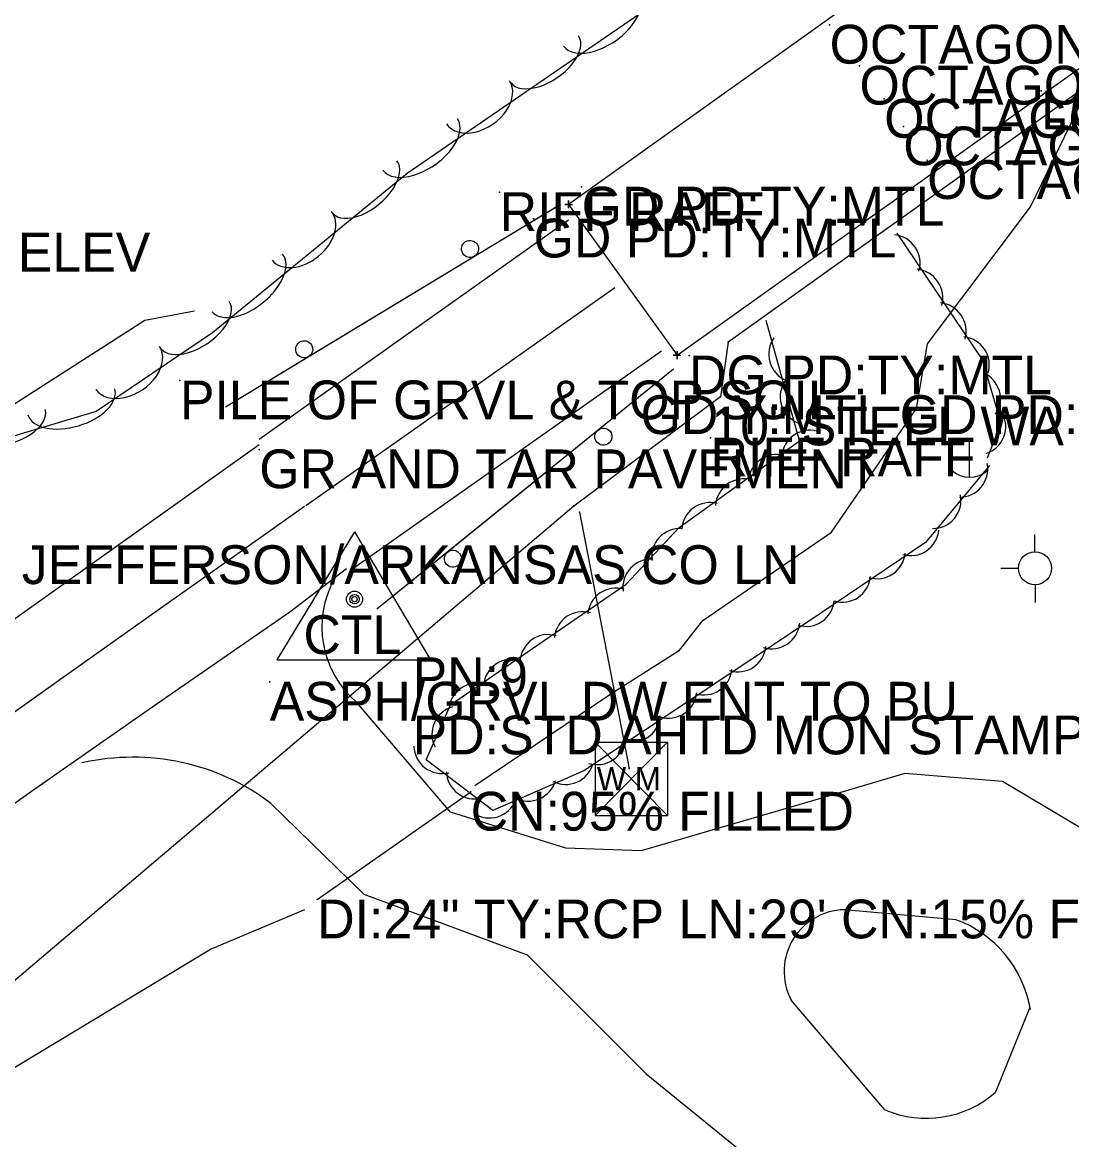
# Model space of a CAD drawing. Extents: x 1451369 to 1458940, y 1868647 to 1875095.
# Drawn here: x 1454143.2 to 1454278.5, y 1871314.6 to 1871458.6 of the extents above; entities that cross this region are included whole.
import ezdxf

# ---------------------------------------------------------------- set-up
doc = ezdxf.new("R2010")
doc.units = 0
for name, color, linetype in [('E_Const Align', 7, 'Continuous'), ('E_Existing_ROW', 7, 'Continuous'), ('E_No Plot', 7, 'Continuous'), ('E_PL and Hook', 7, 'Continuous'), ('E_Proposed ROW and Easements', 7, 'Continuous'), ('E_Quarter Section Line', 7, 'Continuous'), ('E_Row Point', 7, 'Continuous'), ('E_ROW Point Number', 7, 'Continuous'), ('E_Tract Number', 7, 'Continuous'), ('R_No Plot', 7, 'Continuous'), ('S_EDGE_PAVEMENT', 7, 'Continuous'), ('S_EXIST_ROW', 7, 'Continuous'), ('S_GUARDRAIL', 7, 'Continuous'), ('S_MISC_STRUCTURES_ANNOT', 7, 'Continuous'), ('S_PARKING', 7, 'Continuous'), ('S_PAVEMENT_CROWN', 7, 'Continuous'), ('S_PRIMARY_CTL_ANNOT', 7, 'Continuous'), ('S_SECONDARY_CTL_ANNOT', 7, 'Continuous'), ('S_SIDE_DRAIN_ANNOT', 7, 'Continuous'), ('S_SURVEY_TEXT_ANNOT', 7, 'Continuous')]:
    doc.layers.add(name, color=color, linetype=linetype)

msp = doc.modelspace()

# ---------------------------------------------------------------- linework, layer by layer
at = {"layer": 'E_Const Align'}
for p, q in [((1454265.33, 1871404.68), (1454265.33, 1871399.95)), ((1454273.8, 1871390.34), (1454273.8, 1871392.59)), ((1454271.71, 1871388.21), (1454269.39, 1871388.21)), ((1454273.88, 1871383.8), (1454273.88, 1871386.12))]:
    msp.add_line(p, q, dxfattribs=at)
msp.add_circle((1454273.81, 1871388.23), 2.13, dxfattribs=at)
msp.add_arc((1454265.39, 1871403.38), 3.41, 226.3972, 313.6028, dxfattribs=at)
at = {"layer": 'E_Existing_ROW'}
for p, q in [((1454539.16, 1871667.36), (1454213.66, 1871435.13)), ((1454227.64, 1871415.7), (1454553.13, 1871647.85)), ((1454213.66, 1871435.13), (1454227.64, 1871415.7))]:
    msp.add_line(p, q, dxfattribs=at)
at = {"layer": 'E_No Plot'}
for points in [[(1454234.22, 1871417.39), (1454234.22, 1871417.44), (1454234.22, 1871417.39), (1454234.17, 1871417.39), (1454234.22, 1871417.39), (1454234.22, 1871417.34), (1454234.22, 1871417.39), (1454234.27, 1871417.39)], [(1454233.23, 1871410.34), (1454233.23, 1871410.39), (1454233.23, 1871410.34), (1454233.18, 1871410.34), (1454233.23, 1871410.34), (1454233.23, 1871410.29), (1454233.23, 1871410.34), (1454233.28, 1871410.34)], [(1454214.32, 1871396.25), (1454214.32, 1871396.3), (1454214.32, 1871396.25), (1454214.27, 1871396.25), (1454214.32, 1871396.25), (1454214.32, 1871396.2), (1454214.32, 1871396.25), (1454214.37, 1871396.25)], [(1454215.07, 1871395.45), (1454215.07, 1871395.5), (1454215.07, 1871395.45), (1454215.02, 1871395.45), (1454215.07, 1871395.45), (1454215.07, 1871395.4), (1454215.07, 1871395.45), (1454215.12, 1871395.45)], [(1454221.47, 1871362.43), (1454221.47, 1871362.48), (1454221.47, 1871362.43), (1454221.42, 1871362.43), (1454221.47, 1871362.43), (1454221.47, 1871362.38), (1454221.47, 1871362.43), (1454221.52, 1871362.43)]]:
    msp.add_lwpolyline(points, dxfattribs=at)
at = {"layer": 'E_PL and Hook'}
msp.add_line((1454181.23, 1871345.52), (1454201.03, 1871359.41), dxfattribs=at)
at = {"layer": 'E_Proposed ROW and Easements'}
for points in [[(1454247.32, 1871458.28), (1454247.32, 1871458.33), (1454247.32, 1871458.28), (1454247.27, 1871458.28), (1454247.32, 1871458.28), (1454247.32, 1871458.23), (1454247.32, 1871458.28), (1454247.37, 1871458.28)], [(1454251.17, 1871453), (1454251.17, 1871453.05), (1454251.17, 1871453), (1454251.12, 1871453), (1454251.17, 1871453), (1454251.17, 1871452.95), (1454251.17, 1871453), (1454251.22, 1871453)], [(1454254.36, 1871448.73), (1454254.36, 1871448.78), (1454254.36, 1871448.73), (1454254.31, 1871448.73), (1454254.36, 1871448.73), (1454254.36, 1871448.68), (1454254.36, 1871448.73), (1454254.41, 1871448.73)], [(1454274.59, 1871449.79), (1454274.59, 1871449.84), (1454274.59, 1871449.79), (1454274.54, 1871449.79), (1454274.59, 1871449.79), (1454274.59, 1871449.74), (1454274.59, 1871449.79), (1454274.64, 1871449.79)], [(1454256.83, 1871445.17), (1454256.83, 1871445.22), (1454256.83, 1871445.17), (1454256.78, 1871445.17), (1454256.83, 1871445.17), (1454256.83, 1871445.12), (1454256.83, 1871445.17), (1454256.88, 1871445.17)], [(1454259.91, 1871440.83), (1454259.91, 1871440.88), (1454259.91, 1871440.83), (1454259.86, 1871440.83), (1454259.91, 1871440.83), (1454259.91, 1871440.78), (1454259.91, 1871440.83), (1454259.96, 1871440.83)], [(1454215.33, 1871437.41), (1454215.33, 1871437.46), (1454215.33, 1871437.41), (1454215.28, 1871437.41), (1454215.33, 1871437.41), (1454215.33, 1871437.36), (1454215.33, 1871437.41), (1454215.38, 1871437.41)], [(1454204.76, 1871436.71), (1454204.76, 1871436.76), (1454204.76, 1871436.71), (1454204.71, 1871436.71), (1454204.76, 1871436.71), (1454204.76, 1871436.66), (1454204.76, 1871436.71), (1454204.81, 1871436.71)], [(1454209.14, 1871433.29), (1454209.14, 1871433.34), (1454209.14, 1871433.29), (1454209.09, 1871433.29), (1454209.14, 1871433.29), (1454209.14, 1871433.24), (1454209.14, 1871433.29), (1454209.19, 1871433.29)], [(1454229.19, 1871415.65), (1454229.19, 1871415.7), (1454229.19, 1871415.65), (1454229.14, 1871415.65), (1454229.19, 1871415.65), (1454229.19, 1871415.6), (1454229.19, 1871415.65), (1454229.24, 1871415.65)], [(1454163.52, 1871412.43), (1454163.52, 1871412.48), (1454163.52, 1871412.43), (1454163.47, 1871412.43), (1454163.52, 1871412.43), (1454163.52, 1871412.38), (1454163.52, 1871412.43), (1454163.57, 1871412.43)], [(1454222.93, 1871410.53), (1454222.93, 1871410.58), (1454222.93, 1871410.53), (1454222.88, 1871410.53), (1454222.93, 1871410.53), (1454222.93, 1871410.48), (1454222.93, 1871410.53), (1454222.98, 1871410.53)], [(1454232.06, 1871409.07), (1454232.06, 1871409.12), (1454232.06, 1871409.07), (1454232.01, 1871409.07), (1454232.06, 1871409.07), (1454232.06, 1871409.02), (1454232.06, 1871409.07), (1454232.11, 1871409.07)], [(1454231.96, 1871405.06), (1454231.96, 1871405.11), (1454231.96, 1871405.06), (1454231.91, 1871405.06), (1454231.96, 1871405.06), (1454231.96, 1871405.01), (1454231.96, 1871405.06), (1454232.01, 1871405.06)], [(1454173.76, 1871403.54), (1454173.76, 1871403.59), (1454173.76, 1871403.54), (1454173.71, 1871403.54), (1454173.76, 1871403.54), (1454173.76, 1871403.49), (1454173.76, 1871403.54), (1454173.81, 1871403.54)], [(1454175.1, 1871373.59), (1454175.1, 1871373.64), (1454175.1, 1871373.59), (1454175.05, 1871373.59), (1454175.1, 1871373.59), (1454175.1, 1871373.54), (1454175.1, 1871373.59), (1454175.15, 1871373.59)]]:
    msp.add_lwpolyline(points, dxfattribs=at)
at = {"layer": 'E_Quarter Section Line'}
for p, q in [((1454551.64, 1871643.91), (1454234.22, 1871417.39)), ((1454234.22, 1871417.39), (1454233.23, 1871410.34)), ((1454233.23, 1871410.34), (1454214.32, 1871396.25)), ((1454214.32, 1871396.25), (1454074.79, 1871277.88)), ((1454215.07, 1871395.45), (1454221.47, 1871362.43)), ((1454217.09, 1871365.83), (1454226.43, 1871365.83)), ((1454217.09, 1871365.83), (1454217.09, 1871356.34)), ((1454217.09, 1871365.83), (1454226.43, 1871356.34)), ((1454226.43, 1871365.83), (1454217.09, 1871356.34)), ((1454226.43, 1871365.83), (1454226.43, 1871356.34)), ((1454217.09, 1871356.34), (1454226.43, 1871356.34))]:
    msp.add_line(p, q, dxfattribs=at)
at = {"layer": 'E_Row Point'}
for points in [[(1454213.66, 1871435.13), (1454213.66, 1871435.63), (1454213.66, 1871435.13), (1454213.16, 1871435.13), (1454213.66, 1871435.13), (1454213.66, 1871434.63), (1454213.66, 1871435.13), (1454214.16, 1871435.13)], [(1454227.64, 1871415.7), (1454227.64, 1871416.2), (1454227.64, 1871415.7), (1454227.14, 1871415.7), (1454227.64, 1871415.7), (1454227.64, 1871415.2), (1454227.64, 1871415.7), (1454228.14, 1871415.7)]]:
    msp.add_lwpolyline(points, dxfattribs=at)
at = {"layer": 'E_ROW Point Number'}
for points in [[(1454225.87, 1871461.79), (1454192.81, 1871439.12), (1454167.71, 1871418.57), (1454152.7, 1871408.42), (1454126.89, 1871400.74), (1454103.34, 1871384.91), (1454070.96, 1871362.85), (1454039.82, 1871337.12), (1453992.45, 1871296.2)], [(1454255.97, 1871431.42), (1454267.03, 1871415.07), (1454269.41, 1871406.87), (1454267.66, 1871402.4)], [(1454267.92, 1871401.49), (1454259.67, 1871391.55), (1454244.59, 1871381.36), (1454215.62, 1871362.12), (1454203.88, 1871357), (1454195.3, 1871363.52), (1454198.43, 1871370.63), (1454221.09, 1871386.17), (1454227.93, 1871393.48), (1454243.45, 1871404.66), (1454239.13, 1871420.18)]]:
    msp.add_lwpolyline(points, dxfattribs=at)
for centre, major_axis, ratio, start_param, end_param in [((1454217.82, 1871458.85), (4.81, 3.3), 0.553457, 3.14195, 6.283543), ((1454210.56, 1871453.86), (4.38, 3), 0.544019, 3.141939, 6.283532), ((1454201.96, 1871448.28), (4.06, 2.78), 0.689519, 3.142182, 6.283775), ((1454194.52, 1871442.86), (4.81, 3.3), 0.553457, 3.14195, 6.283543), ((1454187.36, 1871437.39), (4.13, 3.38), 0.541116, 3.141699, 6.283292), ((1454179.23, 1871431.08), (3.83, 3.14), 0.685838, 3.141773, 6.283365), ((1454255.41, 1871427.6), (-1.46, 3.34), 0.97664, 4.01115, 5.784351), ((1454172.23, 1871425.01), (4.54, 3.71), 0.550503, 3.141702, 6.283295), ((1454258.34, 1871423.15), (-1.46, 3.34), 0.97664, 4.01115, 5.784351), ((1454165.46, 1871419.61), (4.43, 2.99), 0.541218, 3.14173, 6.283323), ((1454261.35, 1871418.82), (-1.46, 3.34), 0.97664, 4.01115, 5.784351), ((1454156.79, 1871414.06), (4.1, 2.77), 0.685969, 3.141825, 6.283418), ((1454243.11, 1871415.81), (1.32, -3.4), 0.998117, 3.726626, 5.499827), ((1454264.35, 1871414.44), (-1.46, 3.34), 0.97664, 4.01115, 5.784351), ((1454244.59, 1871410.36), (1.32, -3.4), 0.998117, 3.726626, 5.499827), ((1454265.76, 1871410.21), (-2.77, 2.37), 0.966575, 3.229861, 5.003061), ((1454149.51, 1871409.69), (5.61, 1.67), 0.551518, 3.141918, 6.28351), ((1454141.03, 1871407.16), (5.11, 1.52), 0.542113, 3.141907, 6.2835), ((1454266.42, 1871406.46), (2.32, 2.81), 0.98661, 4.147776, 5.920976), ((1454244.76, 1871402.39), (-2.9, -2.21), 0.994873, 3.798568, 5.571768), ((1454240.48, 1871399.26), (-2.9, -2.21), 0.994873, 3.798568, 5.571768), ((1454264.11, 1871401.04), (0.01, 3.64), 0.990642, 3.129535, 4.902736), ((1454236.24, 1871396.12), (-2.9, -2.21), 0.994873, 3.798568, 5.571768), ((1454231.87, 1871393.06), (-2.9, -2.21), 0.994873, 3.798568, 5.571768), ((1454260.66, 1871397), (0.01, 3.64), 0.990642, 3.129535, 4.902736), ((1454228, 1871389.73), (-2.79, -2.34), 0.994444, 3.947383, 5.720584), ((1454257.82, 1871393.5), (0.49, 3.61), 0.988525, 2.977495, 4.750696), ((1454224.28, 1871385.76), (-2.79, -2.34), 0.994444, 3.947383, 5.720584), ((1454253.48, 1871390.52), (0.49, 3.61), 0.988525, 2.977495, 4.750696), ((1454249, 1871387.5), (0.49, 3.61), 0.988525, 2.977495, 4.750696), ((1454219.76, 1871382.05), (-3, -2.07), 0.994943, 3.823064, 5.596264), ((1454244.33, 1871384.38), (0.49, 3.61), 0.988525, 2.977495, 4.750696), ((1454215.44, 1871379), (-3, -2.07), 0.994943, 3.823064, 5.596264), ((1454239.85, 1871381.48), (3.09, 1.93), 0.994984, 3.853895, 5.627096), ((1454211, 1871376.04), (-3, -2.07), 0.994943, 3.823064, 5.596264), ((1454235.49, 1871378.5), (3.09, 1.93), 0.994984, 3.853895, 5.627096), ((1454206.32, 1871372.88), (-3, -2.07), 0.994943, 3.823064, 5.596264), ((1454231.1, 1871375.53), (3.09, 1.93), 0.994984, 3.853895, 5.627096), ((1454201.84, 1871369.8), (-3, -2.07), 0.994943, 3.823064, 5.596264), ((1454226.56, 1871372.53), (3.09, 1.93), 0.994984, 3.853895, 5.627096), ((1454199.66, 1871366.86), (-2.23, -2.88), 0.994565, 4.069944, 5.843145), ((1454221.84, 1871369.43), (3.09, 1.93), 0.994984, 3.853895, 5.627096), ((1454197.33, 1871365.41), (2.9, -2.2), 0.999995, 3.825788, 5.598989), ((1454217.36, 1871366.54), (3.09, 1.93), 0.994984, 3.853895, 5.627096), ((1454213.29, 1871363.99), (2.86, 2.26), 0.995365, 3.566449, 5.33965), ((1454201.53, 1871362.13), (2.9, -2.2), 0.999995, 3.825788, 5.598989), ((1454208.45, 1871361.84), (2.86, 2.26), 0.995365, 3.566449, 5.33965), ((1454203.46, 1871359.67), (2.86, 2.26), 0.995365, 3.566449, 5.33965)]:
    msp.add_ellipse(centre, major_axis=major_axis, ratio=ratio, start_param=start_param, end_param=end_param, dxfattribs=at)
at = {"layer": 'E_Tract Number'}
for points in [[(1454201.03, 1871359.41), (1454201.03, 1871359.46), (1454201.03, 1871359.41), (1454200.98, 1871359.41), (1454201.03, 1871359.41), (1454201.03, 1871359.36), (1454201.03, 1871359.41), (1454201.08, 1871359.41)], [(1454181.23, 1871345.52), (1454181.23, 1871345.57), (1454181.23, 1871345.52), (1454181.18, 1871345.52), (1454181.23, 1871345.52), (1454181.23, 1871345.47), (1454181.23, 1871345.52), (1454181.28, 1871345.52)]]:
    msp.add_lwpolyline(points, dxfattribs=at)
at = {"layer": 'R_No Plot'}
for p, q in [((1454186.04, 1871392.94), (1454176, 1871376.43)), ((1454186.04, 1871392.94), (1454195.86, 1871376.43)), ((1454176, 1871376.43), (1454195.86, 1871376.43))]:
    msp.add_line(p, q, dxfattribs=at)
for radius in [1.04, 0.609, 0.344]:
    msp.add_circle((1454186.04, 1871384.24), radius, dxfattribs=at)
at = {"layer": 'S_EDGE_PAVEMENT'}
for points in [[(1454213.63, 1871433.1), (1454193.68, 1871418.95), (1454173.72, 1871404.81)], [(1454225.62, 1871416.2), (1454205.58, 1871402.08), (1454185.54, 1871387.96)], [(1454173.72, 1871404.14), (1454163.25, 1871396.68), (1454152.79, 1871389.23), (1454142.32, 1871381.77), (1454131.86, 1871374.32), (1454121.32, 1871366.84), (1454110.78, 1871359.35), (1454100.24, 1871351.87), (1454089.7, 1871344.39), (1454078.83, 1871336.64), (1454067.96, 1871328.89), (1454057.09, 1871321.14), (1454046.23, 1871313.39), (1454026.17, 1871298.9), (1454006.11, 1871284.4), (1453989.42, 1871272.42), (1453978.82, 1871264.94), (1453968.21, 1871257.46), (1453957.61, 1871249.98), (1453947.01, 1871242.51), (1453929.87, 1871230.39)], [(1454185.01, 1871388.14), (1454177.7, 1871382.57), (1454160.58, 1871370.75), (1454144.37, 1871359.47), (1454133.32, 1871351.56), (1454122.27, 1871343.65), (1454111.22, 1871335.74), (1454100.17, 1871327.83), (1454089.75, 1871320.21), (1454079.33, 1871312.59), (1454068.91, 1871304.97), (1454058.49, 1871297.35)]]:
    msp.add_lwpolyline(points, dxfattribs=at)
at = {"layer": 'S_EXIST_ROW'}
for points in [[(1454201.55, 1871360.21), (1454219.09, 1871372.04), (1454227.97, 1871377.68), (1454230.98, 1871381.48), (1454247.58, 1871392.86), (1454258.52, 1871408.84), (1454259.95, 1871417.16), (1454273.24, 1871434.8), (1454281.33, 1871451.46)], [(1454165.41, 1871421.39), (1454158.98, 1871420.15), (1454141.36, 1871408.85), (1454123.38, 1871404.07), (1454107.55, 1871392.87), (1454091.72, 1871381.67), (1454077.11, 1871370.25), (1454067.26, 1871358.33), (1454056.22, 1871351.03), (1454045.19, 1871343.73), (1454027.6, 1871335.62)], [(1454064.7, 1871271.29), (1454076.94, 1871279.19), (1454094.28, 1871290.8), (1454111.61, 1871302.41), (1454122.07, 1871310.24), (1454132.53, 1871318.08), (1454149.99, 1871328.61), (1454167.45, 1871339.14), (1454179.62, 1871344.24)]]:
    msp.add_lwpolyline(points, dxfattribs=at)
at = {"layer": 'S_GUARDRAIL'}
for points in [[(1454169.42, 1871409.05), (1454212.61, 1871435.16)], [(1454201.5, 1871428.45), (1454212.2, 1871434.91)], [(1454212.2, 1871434.91), (1454212.61, 1871435.16)], [(1454180.11, 1871415.51), (1454201.5, 1871428.45)], [(1454169.42, 1871409.05), (1454180.11, 1871415.51)], [(1454227.18, 1871413.91), (1454188.93, 1871382.95)], [(1454227.18, 1871413.91), (1454217.46, 1871406.04)], [(1454217.46, 1871406.04), (1454198.03, 1871390.32)], [(1454198.03, 1871390.32), (1454188.93, 1871382.95)]]:
    msp.add_lwpolyline(points, dxfattribs=at)
for centre, major_axis, ratio in [((1454200.94, 1871429.39), (-0.569, 0.941), 0.999726), ((1454179.55, 1871416.46), (-0.569, 0.941), 0.999726), ((1454218.15, 1871405.19), (0.692, -0.855), 0.999754), ((1454198.73, 1871389.46), (0.692, -0.855), 0.999754)]:
    msp.add_ellipse(centre, major_axis=major_axis, ratio=ratio, dxfattribs=at)
at = {"layer": 'S_PARKING'}
for points in [[(1454175.25, 1871357.91), (1454187.26, 1871346.22), (1454208.3, 1871338.38), (1454223.66, 1871323.05), (1454242.1, 1871308.07), (1454266.52, 1871302.24), (1454282.9, 1871301.24), (1454315.4, 1871284.76), (1454323.88, 1871297.21), (1454314.37, 1871309.59), (1454301.45, 1871328.71), (1454286.62, 1871350.64), (1454269.62, 1871360.74), (1454257.03, 1871361.79), (1454244.36, 1871358.02), (1454223, 1871351.82), (1454213.28, 1871352.13), (1454198.42, 1871356.78), (1454186.28, 1871370.97)], [(1454249.71, 1871344.21), (1454263.62, 1871342.93)], [(1454254.46, 1871318.42), (1454242.36, 1871332.55)], [(1454273.11, 1871331.52), (1454268.73, 1871320.7)]]:
    msp.add_lwpolyline(points, dxfattribs=at)
for centre, major_axis, ratio, start_param, end_param in [((1454194.76, 1871380.75), (-11.35, -6.24), 0.991148, 5.277088, 6.640236), ((1454157.12, 1871337.62), (-28.17, -2.01), 0.928959, 3.948685, 4.868976), ((1454249.38, 1871336.26), (0.92, -7.9), 0.997151, 2.982967, 5.081863), ((1454259.53, 1871329.58), (-8.08, 11.96), 0.947327, 4.268711, 5.365549), ((1454259.8, 1871330.81), (13.18, 2.91), 0.999374, 4.08859, 5.218461)]:
    msp.add_ellipse(centre, major_axis=major_axis, ratio=ratio, start_param=start_param, end_param=end_param, dxfattribs=at)
at = {"layer": 'S_PAVEMENT_CROWN'}
for points in [[(1454219.62, 1871424.37), (1454199.86, 1871410.43), (1454179.78, 1871396.27)], [(1454179.61, 1871396.18), (1454169.23, 1871388.84), (1454158.84, 1871381.49), (1454148.46, 1871374.14), (1454138.08, 1871366.8), (1454127.34, 1871359.17), (1454116.6, 1871351.55), (1454105.86, 1871343.93), (1454095.11, 1871336.3), (1454084.38, 1871328.63), (1454073.65, 1871320.95), (1454062.91, 1871313.27), (1454052.18, 1871305.6), (1454041.79, 1871298.22), (1454031.39, 1871290.85), (1454021, 1871283.47), (1454010.6, 1871276.1), (1453994.45, 1871264.5), (1453984.08, 1871257.16), (1453973.71, 1871249.81), (1453963.34, 1871242.47), (1453952.97, 1871235.12), (1453935.67, 1871223.29)]]:
    msp.add_lwpolyline(points, dxfattribs=at)

# ---------------------------------------------------------------- texts
at = {"layer": 'E_Quarter Section Line'}
msp.add_text('W M', height=3, rotation=360, dxfattribs=at).set_placement((1454217.3, 1871359.6))
at = {"layer": 'R_No Plot'}
msp.add_text('CTL', height=5, rotation=360, dxfattribs=at).set_placement((1454179.45, 1871377.17))
at = {"layer": 'S_MISC_STRUCTURES_ANNOT'}
for s, p in [('OCTAGON CONC COLUMN 17"', (1454247.32, 1871453.28)), ('OCTAGON CONC COLUMN 17"', (1454251.17, 1871448)), ('OCTAGON CONC COLUMN 17"', (1454254.36, 1871443.73)), ('LOW STEEL', (1454274.59, 1871444.79)), ('OCTAGON CONC COLUMN 17"', (1454256.83, 1871440.17)), ('OCTAGON CONC COLUMN 17"', (1454259.91, 1871435.83))]:
    msp.add_text(s, height=5, dxfattribs=at).set_placement(p)
at = {"layer": 'S_PRIMARY_CTL_ANNOT'}
for s, p in [('PN:9', (1454193.54, 1871371.74)), ('PD:STD AHTD MON STAMPED PN:9 11', (1454193.54, 1871364.24))]:
    msp.add_text(s, height=5, dxfattribs=at).set_placement(p)
at = {"layer": 'S_SECONDARY_CTL_ANNOT'}
msp.add_text('PD:8 SPIKE TRIG ELEV', height=5, dxfattribs=at).set_placement((1454086.5, 1871426.48))
at = {"layer": 'S_SIDE_DRAIN_ANNOT'}
for s, p in [('CN:95% FILLED', (1454201.03, 1871354.41)), ('DI:24" TY:RCP LN:29\' CN:15% FIL', (1454181.23, 1871340.52))]:
    msp.add_text(s, height=5, dxfattribs=at).set_placement(p)
at = {"layer": 'S_SURVEY_TEXT_ANNOT'}
for s, p in [('GD PD:TY:MTL', (1454215.33, 1871432.41)), ('RIFF RAFF', (1454204.76, 1871431.71)), ('GD PD:TY:MTL', (1454209.14, 1871428.29)), ('DG PD:TY:MTL', (1454229.19, 1871410.65)), ('PILE OF GRVL & TOP SOIL', (1454163.52, 1871407.43)), ('GD Y:MTL GD PD:TY:MTL', (1454222.93, 1871405.53)), ('10" STEEL WA', (1454232.06, 1871404.07)), ('RIFF RAFF', (1454231.96, 1871400.06)), ('GR AND TAR PAVEMENT', (1454173.76, 1871398.54)), ('JEFFERSON/ARKANSAS CO LN', (1454143.12, 1871386.19)), ('ASPH/GRVL DW ENT TO BU', (1454175.1, 1871368.59))]:
    msp.add_text(s, height=5, dxfattribs=at).set_placement(p)

doc.saveas('drawing.dxf')
